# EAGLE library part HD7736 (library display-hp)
LED DISPLAY + - 1/2 character, decimal point right
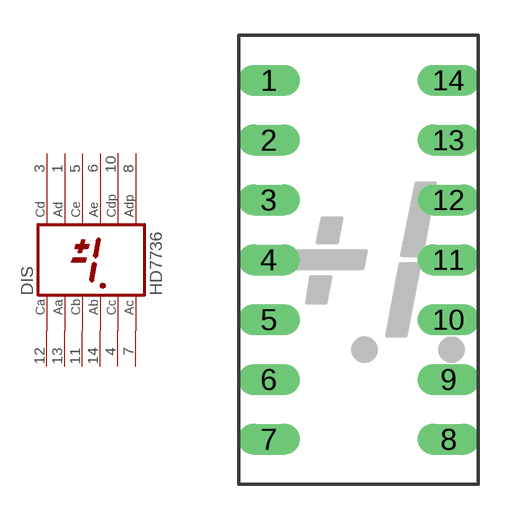
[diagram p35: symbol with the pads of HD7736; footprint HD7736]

Designator prefix DIS

## HD7736 (OC_FARNELL: unknown; OC_NEWARK: unknown)  [HD7736]
1  AD  pas
3  CD  pas
4  CC  pas
5  CE  pas
6  AE  pas
7  AC  pas
8  ADP  pas
10  CDP  pas
11  CB  pas
12  CA  pas
13  AA  pas
14  AB  pas

## Footprint HD7736 (pad centres in mm)
LED DISPLAY 8-mm + - 1/2 character, 2 decimal points
drill 0.813 long: 1 -3.81,7.62; 2 -3.81,5.08; 3 -3.81,2.54; 4 -3.81,0; 5 -3.81,-2.54; 6 -3.81,-5.08; 7 -3.81,-7.62; 8 3.81,-7.62; 9 3.81,-5.08; 10 3.81,-2.54; 11 3.81,0; 12 3.81,2.54; 13 3.81,5.08; 14 3.81,7.62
